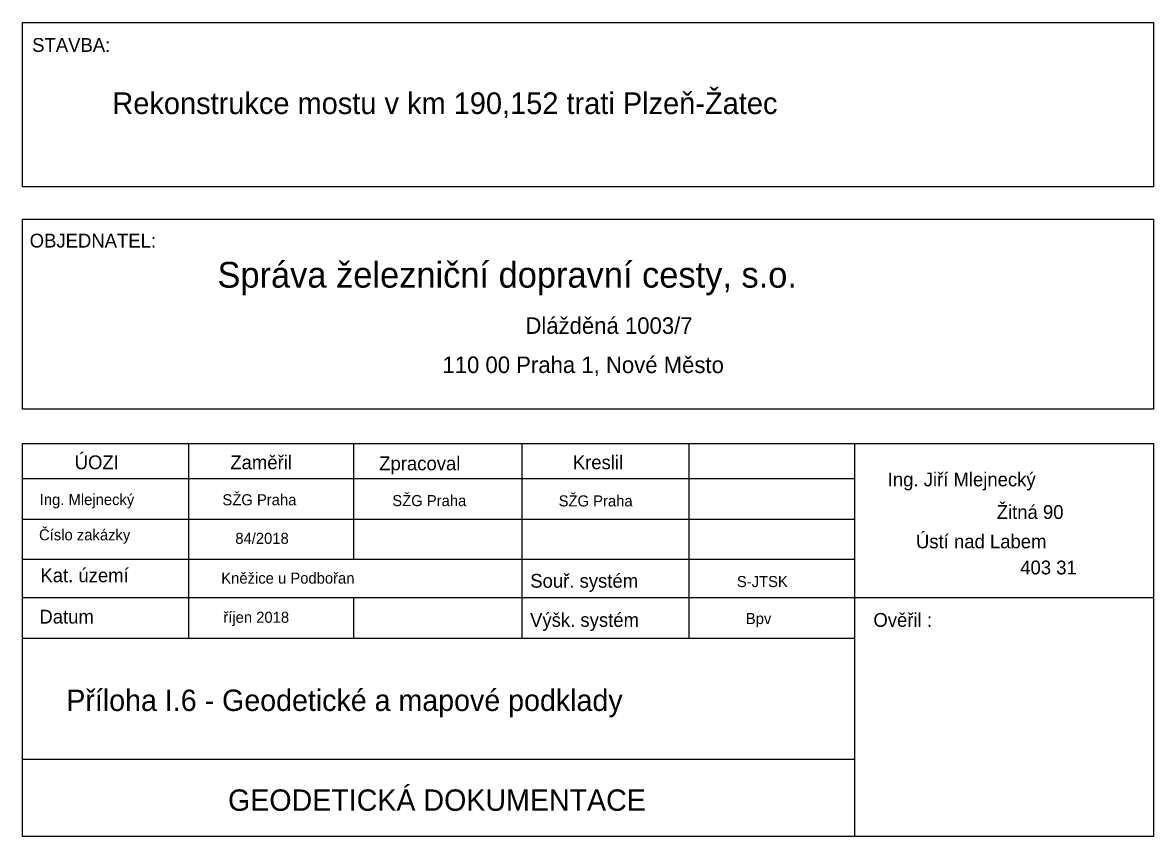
# Model space of a CAD drawing. Extents: x -879530 to -879371, y -1019242 to -1019127.
import ezdxf

# ---------------------------------------------------------------- set-up
doc = ezdxf.new("R2010")
doc.units = 0
doc.layers.add('LEGENDA', color=7, linetype='Continuous')
doc.layers.add('tabulka', color=7, linetype='Continuous')

msp = doc.modelspace()

# ---------------------------------------------------------------- linework, layer by layer
at = {"layer": 'tabulka'}
for p, q in [((-879530.09, -1019186.45), (-879371.44, -1019186.45)), ((-879506.8, -1019186.45), (-879506.8, -1019213.77)), ((-879483.66, -1019186.45), (-879483.66, -1019202.65)), ((-879460.06, -1019186.45), (-879460.06, -1019213.77)), ((-879436.61, -1019186.45), (-879436.61, -1019213.77)), ((-879413.31, -1019241.58), (-879413.31, -1019186.45)), ((-879530.09, -1019191.36), (-879413.31, -1019191.36)), ((-879530.09, -1019197.07), (-879413.31, -1019197.07)), ((-879530.09, -1019202.65), (-879413.31, -1019202.65)), ((-879530.09, -1019208.07), (-879371.44, -1019208.07)), ((-879483.66, -1019208.07), (-879483.66, -1019213.77)), ((-879530.09, -1019213.77), (-879413.31, -1019213.77)), ((-879530.09, -1019230.76), (-879413.31, -1019230.76))]:
    msp.add_line(p, q, dxfattribs=at)
for points in [[(-879530.09, -1019127.36), (-879371.44, -1019127.36), (-879371.44, -1019150.43), (-879530.09, -1019150.43)], [(-879530.09, -1019154.95), (-879371.44, -1019154.95), (-879371.44, -1019181.64), (-879530.09, -1019181.64)]]:
    msp.add_lwpolyline(points, close=True, dxfattribs=at)
msp.add_lwpolyline([(-879371.44, -1019186.45), (-879371.44, -1019241.58), (-879530.09, -1019241.58), (-879530.09, -1019186.45)], dxfattribs=at)

# ---------------------------------------------------------------- texts
at = {"layer": 'LEGENDA'}
msp.add_text('Rekonstrukce mostu v km 190,152 trati Plzeň-Žatec', height=3.04, dxfattribs=at).set_placement((-879517.5, -1019140.2))
at = {"layer": 'tabulka'}
for s, height, p in [('STAVBA:', 1.94, (-879528.75, -1019131.47)), ('OBJEDNATEL:', 1.94, (-879529.1, -1019158.93)), ('Správa železniční dopravní cesty, s.o.', 3.61, (-879502.75, -1019164.56)), ('Dlážděná 1003/7', 2.32, (-879459.55, -1019171.05)), ('110 00 Praha 1, Nové Město', 2.32, (-879471.19, -1019176.55)), ('ÚOZI', 1.94, (-879522.79, -1019190.05)), ('Zaměřil', 1.94, (-879500.95, -1019190.05)), ('Zpracoval', 1.94, (-879480.06, -1019190.2)), ('Kreslil', 1.94, (-879452.9, -1019190.05)), ('Ing. Jiří Mlejnecký', 1.94, (-879408.71, -1019192.45)), ('Ing. Mlejnecký', 1.552, (-879527.69, -1019195.08)), ('SŽG Praha', 1.552, (-879502.06, -1019195.11)), ('SŽG Praha', 1.552, (-879478.22, -1019195.23)), ('SŽG Praha', 1.552, (-879454.88, -1019195.27)), ('Žitná 90', 1.94, (-879393.42, -1019197.03)), ('Číslo zakázky', 1.552, (-879527.79, -1019200.03)), ('84/2018', 1.552, (-879500.25, -1019200.52)), ('Ústí nad Labem', 1.94, (-879404.75, -1019201.15)), ('403 31', 1.94, (-879390.12, -1019204.81)), ('Kat. území', 1.94, (-879527.6, -1019205.91)), ('Kněžice u Podbořan', 1.552, (-879502.22, -1019206.11)), ('Souř. systém', 1.94, (-879458.87, -1019206.68)), ('S-JTSK', 1.552, (-879429.88, -1019206.59)), ('Datum', 1.94, (-879527.74, -1019211.71)), ('říjen 2018', 1.552, (-879501.93, -1019211.6)), ('Výšk. systém', 1.94, (-879458.89, -1019212.17)), ('Bpv', 1.552, (-879428.62, -1019211.78)), ('Ověřil :', 1.94, (-879410.72, -1019212.17)), ('Příloha I.6 - Geodetické a mapové podklady', 3, (-879523.96, -1019223.98)), ('GEODETICKÁ DOKUMENTACE ', 3, (-879501.27, -1019237.99))]:
    msp.add_text(s, height=height, dxfattribs=at).set_placement(p)

doc.saveas('drawing.dxf')
